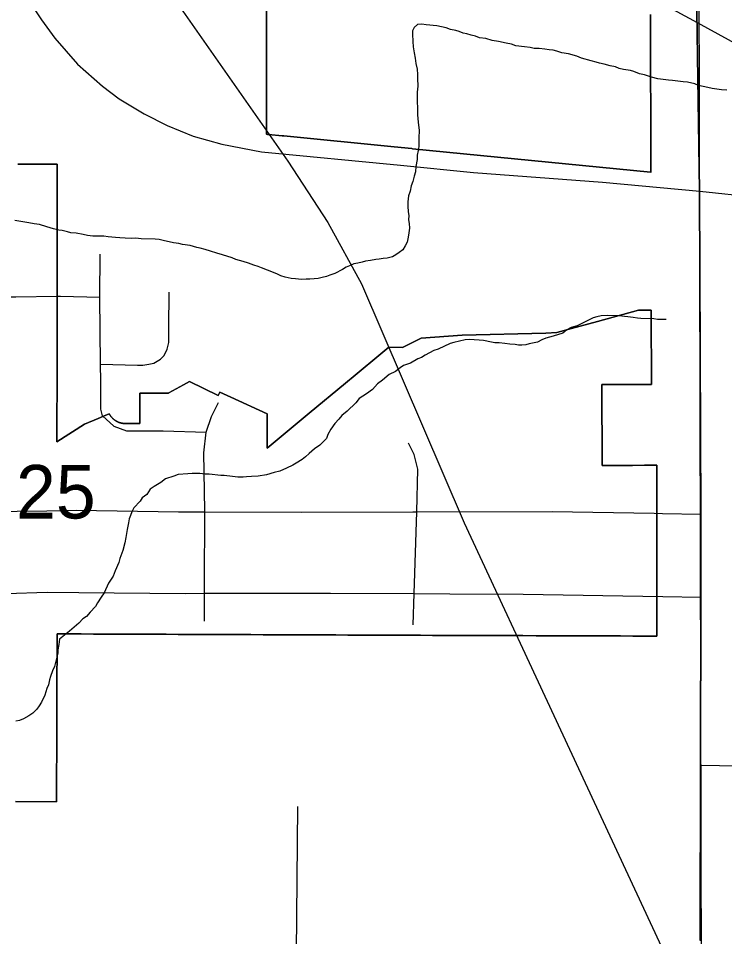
# Model space of a CAD drawing. Extents: x 0 to 34, y 0 to 22.
# Drawn here: x 2.497 to 3.049, y 18.646 to 19.364 of the extents above; entities that cross this region are included whole.
import ezdxf

# ---------------------------------------------------------------- set-up
doc = ezdxf.new("R2010")
doc.units = 0
for name, color, linetype in [('Default', 7, 'Continuous'), ('GM_X_City_Street', 7, 'Continuous'), ('GM_X_County_Road', 7, 'Continuous'), ('GM_X_Minor_River', 7, 'Continuous'), ('GM_X_Rail_Line', 7, 'Continuous'), ('GM_X_Section', 7, 'Continuous'), ('GM_X_Section_Text', 7, 'Continuous'), ('GM_X_State_Route', 7, 'Continuous'), ('GM_X_Township_Road', 7, 'Continuous')]:
    doc.layers.add(name, color=color, linetype=linetype)

msp = doc.modelspace()

# ---------------------------------------------------------------- linework, layer by layer
at = {"layer": 'Default'}
msp.add_lwpolyline([(2.1, 19.52883), (2.1, 18.51562), (3.03099, 18.49904), (3.02863, 19.51298)], close=True, dxfattribs=at)
at = {"layer": 'GM_X_City_Street'}
for p, q in [((2.52978, 19.14672), (2.56036, 19.14584)), ((3.00023, 18.97676), (3.03034, 18.97621)), ((3.00062, 18.91183), (3.03043, 18.9113))]:
    msp.add_line(p, q, dxfattribs=at)
for points in [[(2.5625, 19.05323), (2.56115, 19.05834), (2.56115, 19.08038), (2.561, 19.09346), (2.56036, 19.14584), (2.56062, 19.17953)], [(2.38459, 19.14607), (2.48317, 19.14612), (2.49488, 19.1463), (2.52672, 19.14681), (2.52978, 19.14672)], [(2.561, 19.09346), (2.58987, 19.09281), (2.59411, 19.09281), (2.59866, 19.09346), (2.60256, 19.09444), (2.60777, 19.09736), (2.6107, 19.1003), (2.61298, 19.10518), (2.61427, 19.11038), (2.61427, 19.12209), (2.6146, 19.14975)], [(2.64242, 18.97904), (2.64165, 19.02416), (2.64349, 19.04031), (2.64777, 19.05255), (2.65325, 19.06347)], [(2.5625, 19.05323), (2.57136, 19.04511), (2.58126, 19.04139), (2.61007, 19.04134), (2.64349, 19.04031)], [(2.80525, 18.88961), (2.80604, 18.91404), (2.80813, 18.97807), (2.80902, 19.01141), (2.80617, 19.02284), (2.80175, 19.03164)], [(2.33184, 18.8818), (2.34681, 18.88432), (2.3594, 18.88907), (2.37208, 18.90064), (2.39638, 18.92723), (2.41716, 18.94704), (2.43594, 18.96043), (2.45887, 18.97223), (2.48285, 18.97833), (2.49577, 18.97855), (2.51894, 18.97894)], [(2.51894, 18.97894), (2.542, 18.97934), (2.62199, 18.97814), (2.64244, 18.97808), (2.71827, 18.97784), (2.8051, 18.97806), (2.80813, 18.97807), (2.91391, 18.97833), (2.99369, 18.97688), (3.00023, 18.97676)], [(2.64233, 18.92108), (2.64244, 18.97808), (2.64242, 18.97904)], [(2.64227, 18.89242), (2.64232, 18.91432), (2.64233, 18.92108)], [(2.48716, 18.91411), (2.5194, 18.91514), (2.5441, 18.91495), (2.62706, 18.91429), (2.64232, 18.91432), (2.7408, 18.91449), (2.80604, 18.91404), (2.83405, 18.91385), (2.8913, 18.91376), (3.00062, 18.91183)], [(3.0302, 18.77983), (3.08849, 18.77885)], [(2.70841, 18.23919), (2.70934, 18.31177), (2.71042, 18.36903), (2.71381, 18.49764), (2.71286, 18.54198), (2.71361, 18.57587), (2.71511, 18.74755)]]:
    msp.add_lwpolyline(points, dxfattribs=at)
at = {"layer": 'GM_X_County_Road'}
for points in [[(3.02999, 18.64245), (3.0302, 18.77983), (3.03043, 18.9113), (3.03034, 18.97621), (3.02936, 19.22884), (3.02669, 19.40438)], [(2.50468, 19.37914), (2.50867, 19.37231), (2.51483, 19.36302), (2.52516, 19.34852), (2.54294, 19.32817), (2.56261, 19.31107), (2.57559, 19.30121), (2.59503, 19.28936), (2.61314, 19.28035), (2.63333, 19.27201), (2.6558, 19.26556), (2.6867, 19.25968), (2.79553, 19.24926), (2.85242, 19.24357), (2.95349, 19.23583), (3.02936, 19.22884)], [(3.02936, 19.22884), (3.07337, 19.22422), (3.10249, 19.21759), (3.13603, 19.20469), (3.1762, 19.1811), (3.20348, 19.15936), (3.21785, 19.14093), (3.26171, 19.08417), (3.29193, 19.05247), (3.33026, 19.0193), (3.37673, 18.9946), (3.41025, 18.98155), (3.46132, 18.96116), (3.5057, 18.94301), (3.5468, 18.92932), (3.57861, 18.91839), (3.61208, 18.90708), (3.66245, 18.88858), (3.70593, 18.87324), (3.73173, 18.8659), (3.81438, 18.84158)]]:
    msp.add_lwpolyline(points, dxfattribs=at)
at = {"layer": 'GM_X_Minor_River'}
for points in [[(3.05043, 19.30778), (3.04626, 19.30823), (3.03907, 19.30912), (3.03566, 19.30994), (3.02848, 19.31159), (3.02547, 19.31278), (3.0198, 19.31403), (3.01639, 19.31446), (3.00805, 19.31537), (3.00503, 19.31581), (2.99669, 19.31672), (2.99178, 19.31794), (2.98612, 19.31995), (2.98234, 19.32077), (2.97782, 19.32237), (2.97517, 19.32318), (2.96988, 19.32403), (2.96647, 19.32486), (2.96346, 19.32605), (2.9593, 19.32689), (2.95477, 19.3281), (2.95099, 19.32893), (2.94834, 19.32974), (2.94457, 19.33095), (2.93702, 19.33298), (2.93325, 19.33457), (2.92683, 19.3362), (2.92153, 19.33706), (2.91775, 19.33827), (2.91473, 19.33908), (2.91171, 19.33952), (2.9083, 19.33996), (2.90375, 19.34042), (2.89996, 19.34048), (2.89693, 19.3413), (2.89239, 19.34176), (2.88557, 19.34264), (2.88218, 19.34384), (2.87802, 19.34467), (2.87197, 19.34592), (2.86705, 19.34677), (2.86214, 19.34838), (2.85721, 19.34885), (2.8542, 19.35004), (2.8508, 19.35086), (2.84741, 19.35206), (2.84438, 19.3525), (2.84136, 19.35369), (2.83872, 19.3545), (2.83456, 19.35533), (2.83117, 19.35653), (2.82399, 19.35818), (2.81565, 19.35909), (2.81224, 19.35953), (2.80882, 19.35921), (2.80612, 19.35698), (2.80493, 19.35434), (2.80489, 19.35168), (2.80516, 19.34597), (2.80546, 19.34178), (2.80614, 19.33721), (2.80682, 19.33302)], [(2.80682, 19.33302), (2.8075, 19.32882), (2.80855, 19.32424), (2.80886, 19.32006), (2.8088, 19.31702), (2.80907, 19.31093), (2.8086, 19.30638), (2.80845, 19.29802), (2.80877, 19.29497), (2.80865, 19.28851), (2.80931, 19.2828), (2.80995, 19.27632), (2.80984, 19.27062), (2.80978, 19.26721), (2.80972, 19.26378), (2.80928, 19.26075), (2.80845, 19.25696), (2.80839, 19.25354), (2.80753, 19.24824), (2.80707, 19.24407), (2.80625, 19.24066), (2.80504, 19.2365), (2.80384, 19.2331), (2.803, 19.22893), (2.80179, 19.22515), (2.80133, 19.2206), (2.80126, 19.21718), (2.80156, 19.21261), (2.80189, 19.20995), (2.80183, 19.20653), (2.80215, 19.20348), (2.80246, 19.20005), (2.80202, 19.19626), (2.80157, 19.19285), (2.80075, 19.18906), (2.79917, 19.18605), (2.79722, 19.18304), (2.79452, 19.18081), (2.79183, 19.17896), (2.78914, 19.17748), (2.78495, 19.17642), (2.7819, 19.17609), (2.77886, 19.17577), (2.7762, 19.17543), (2.77201, 19.17475), (2.7682, 19.17405), (2.76553, 19.17334), (2.7621, 19.17264), (2.75905, 19.17194), (2.75561, 19.17048), (2.75293, 19.16939), (2.75024, 19.16753), (2.74411, 19.1646), (2.74029, 19.16315), (2.73761, 19.16205), (2.73418, 19.16135), (2.73114, 19.16065), (2.72809, 19.16032), (2.72467, 19.16), (2.72163, 19.16006), (2.71821, 19.15974), (2.71328, 19.16021), (2.70988, 19.16065), (2.70534, 19.16149), (2.70194, 19.16269), (2.69931, 19.16388), (2.69479, 19.16586), (2.6914, 19.16706), (2.68688, 19.16904), (2.68424, 19.16985), (2.68084, 19.17105), (2.6767, 19.17264), (2.67254, 19.17385), (2.66952, 19.17467), (2.66688, 19.17548), (2.66386, 19.17667), (2.65632, 19.17908), (2.65178, 19.18031), (2.64688, 19.18191), (2.64273, 19.18313), (2.63895, 19.18433), (2.6363, 19.18476), (2.63102, 19.18638), (2.62496, 19.18725), (2.62232, 19.18805), (2.61815, 19.18851), (2.60983, 19.19017), (2.60681, 19.19099), (2.60378, 19.19142), (2.59278, 19.19162), (2.58861, 19.19207), (2.58481, 19.19176), (2.58026, 19.19222), (2.57609, 19.19229), (2.57268, 19.19274), (2.56699, 19.19322), (2.56359, 19.19366), (2.55486, 19.19381), (2.55069, 19.19427), (2.54729, 19.19509), (2.54199, 19.19594)], [(2.54199, 19.19594), (2.53782, 19.1964), (2.53518, 19.1972), (2.53102, 19.19804), (2.52837, 19.19846), (2.52421, 19.1993), (2.51893, 19.20091), (2.51327, 19.20292), (2.5091, 19.20337), (2.50494, 19.2042), (2.497, 19.20549), (2.49397, 19.20592)], [(3.00308, 19.12844), (2.99625, 19.12857), (2.99361, 19.12899), (2.98336, 19.12917), (2.98071, 19.1296), (2.9773, 19.13004), (2.97314, 19.1305), (2.97049, 19.13092), (2.96632, 19.13138), (2.95721, 19.13154), (2.95227, 19.13125), (2.94884, 19.13055), (2.94617, 19.12984), (2.94081, 19.12727), (2.9366, 19.12507), (2.93353, 19.1236), (2.92895, 19.12216), (2.9255, 19.12032), (2.92241, 19.11771), (2.91478, 19.11557), (2.90906, 19.11377), (2.906, 19.11268), (2.90255, 19.11085), (2.89607, 19.10944), (2.8934, 19.10873), (2.89036, 19.1084), (2.8877, 19.10845), (2.88505, 19.10888), (2.88088, 19.10933), (2.8771, 19.10978), (2.87255, 19.11024), (2.86913, 19.1103), (2.86649, 19.11073), (2.86044, 19.11197), (2.85703, 19.11242), (2.84907, 19.11294), (2.84602, 19.11261), (2.83725, 19.11049), (2.8342, 19.10978), (2.82501, 19.10538), (2.82158, 19.1043), (2.81467, 19.10063), (2.81198, 19.09877), (2.80893, 19.09769), (2.80317, 19.09437), (2.79782, 19.09256), (2.79513, 19.09071), (2.79166, 19.08773), (2.78669, 19.08554), (2.78129, 19.08107), (2.77744, 19.0781), (2.77356, 19.07361), (2.76894, 19.07027), (2.76318, 19.06657), (2.76046, 19.0632), (2.75389, 19.05685), (2.74965, 19.05351), (2.74732, 19.05051), (2.74422, 19.04714), (2.7411, 19.04264), (2.73875, 19.0385), (2.73755, 19.03548), (2.73252, 19.03025), (2.72829, 19.02728), (2.72405, 19.02355), (2.72134, 19.02094), (2.71865, 19.01909), (2.71404, 19.01613), (2.71136, 19.01466), (2.70638, 19.01208), (2.70102, 19.0099), (2.69683, 19.00883), (2.69072, 19.00704), (2.68425, 19.00601), (2.67893, 19.00573), (2.67513, 19.00542), (2.67246, 19.00508), (2.66829, 19.00516), (2.66412, 19.00561), (2.65768, 19.00649), (2.65503, 19.00653), (2.64594, 19.00746), (2.6429, 19.00751), (2.63873, 19.00796), (2.63266, 19.00807), (2.62924, 19.00775), (2.62164, 19.00713), (2.6182, 19.00605), (2.61171, 19.00389), (2.60824, 19.0009), (2.60287, 18.99796), (2.59979, 18.99573), (2.59706, 18.9916), (2.59359, 18.989), (2.59202, 18.98637), (2.587, 18.98114), (2.58581, 18.9785), (2.58342, 18.97246), (2.58298, 18.96942), (2.58175, 18.96412), (2.58087, 18.95806)], [(2.58087, 18.95806), (2.58004, 18.95389), (2.57841, 18.94784), (2.57601, 18.94142), (2.5752, 18.93839), (2.57242, 18.93198), (2.57082, 18.92783), (2.5673, 18.92219), (2.56375, 18.91465), (2.56141, 18.91127), (2.55867, 18.90676), (2.5571, 18.90412), (2.55284, 18.89964), (2.55013, 18.89626), (2.54706, 18.89442), (2.54396, 18.89105), (2.53663, 18.88472), (2.52892, 18.8784), (2.52846, 18.87422), (2.52763, 18.87006), (2.52758, 18.8674), (2.52511, 18.85718), (2.52353, 18.85379), (2.52193, 18.84925), (2.52112, 18.84661), (2.52029, 18.84282), (2.5191, 18.8398), (2.51748, 18.83451), (2.51472, 18.82923), (2.51315, 18.82622), (2.5112, 18.8236), (2.50811, 18.82061), (2.50503, 18.81838), (2.50082, 18.81618), (2.49775, 18.81471), (2.49471, 18.81439)]]:
    msp.add_lwpolyline(points, dxfattribs=at)
at = {"layer": 'GM_X_Rail_Line'}
for points in [[(4.43224, 18.5911), (4.35401, 18.63374), (4.03896, 18.80642), (3.93636, 18.86252), (3.55446, 19.07184), (3.44627, 19.13121), (3.32905, 19.19548), (3.23414, 19.24733), (3.176, 19.27923), (3.12462, 19.30736), (3.02751, 19.36047), (2.90102, 19.42945), (2.74452, 19.51493), (2.65716, 19.56269), (2.57906, 19.60512), (2.43608, 19.68368), (2.39019, 19.70835), (2.24327, 19.78828)], [(2.38979, 19.70642), (2.70747, 19.25227), (2.73877, 19.20427), (2.76499, 19.15627), (2.84522, 18.96957), (3.19576, 18.2158), (3.25099, 18.10144), (3.28001, 18.04099), (3.32836, 17.99747), (3.36946, 17.95879), (3.44441, 17.92253), (3.72704, 17.80395), (4.02347, 17.68367)]]:
    msp.add_lwpolyline(points, dxfattribs=at)
at = {"layer": 'GM_X_Section'}
msp.add_lwpolyline([(3.02863, 19.51298), (4.05087, 19.50181), (4.05276, 18.48869), (3.03099, 18.49904)], close=True, dxfattribs=at)
at = {"layer": 'GM_X_State_Route'}
for points in [[(2.991, 19.36707), (2.99121, 19.24447), (2.99121, 19.2436), (2.99083, 19.24364), (2.80494, 19.26209), (2.80423, 19.26216), (2.79063, 19.26351), (2.7043, 19.27204), (2.70309, 19.27216), (2.69219, 19.27323), (2.69148, 19.2733), (2.69065, 19.27338), (2.69065, 19.27558), (2.69065, 19.29284), (2.69063, 19.37613)], [(2.69063, 19.37613), (2.69065, 19.29284), (2.69065, 19.29061), (2.69065, 19.27558), (2.69065, 19.27338), (2.69148, 19.2733), (2.69219, 19.27323), (2.70309, 19.27216), (2.7043, 19.27204), (2.79063, 19.26351), (2.80423, 19.26216), (2.80494, 19.26209), (2.99083, 19.24364), (2.99121, 19.24447), (2.991, 19.36707)], [(2.49635, 19.25005), (2.52713, 19.25012), (2.52715, 19.21206), (2.52716, 19.17687), (2.52714, 19.17403), (2.52713, 19.16551), (2.52711, 19.15131), (2.5271, 19.14663), (2.52709, 19.14184), (2.52707, 19.1276), (2.52705, 19.11627), (2.52703, 19.1049), (2.52703, 19.10431), (2.52702, 19.09354), (2.52701, 19.09266), (2.527, 19.08218), (2.527, 19.08101), (2.52698, 19.07081), (2.52698, 19.06936), (2.52696, 19.05789), (2.52696, 19.05772), (2.52694, 19.04607), (2.52692, 19.03442), (2.52692, 19.03281), (2.54856, 19.0467), (2.55905, 19.05108), (2.56335, 19.05288), (2.5678, 19.05474), (2.56804, 19.05431), (2.56817, 19.05409), (2.56829, 19.05388), (2.56842, 19.05367), (2.56856, 19.05346), (2.5687, 19.05326), (2.56884, 19.05305), (2.56899, 19.05285), (2.56914, 19.05266), (2.56929, 19.05246), (2.56944, 19.05227), (2.5696, 19.05208), (2.56977, 19.05189), (2.56993, 19.05171), (2.5701, 19.05152), (2.57036, 19.05126), (2.57054, 19.05108), (2.57072, 19.05091), (2.5709, 19.05074), (2.57109, 19.05058), (2.57128, 19.05042), (2.57147, 19.05026), (2.57166, 19.05011), (2.57186, 19.04996), (2.57206, 19.04981), (2.57226, 19.04966), (2.57246, 19.04952), (2.57267, 19.04939), (2.57288, 19.04925), (2.57309, 19.04912), (2.5733, 19.049), (2.57352, 19.04888), (2.57374, 19.04876), (2.57396, 19.04864), (2.57418, 19.04853), (2.5744, 19.04843), (2.57463, 19.04832), (2.57486, 19.04822), (2.57508, 19.04813), (2.57532, 19.04804), (2.57555, 19.04795), (2.57578, 19.04787), (2.57602, 19.04779), (2.57625, 19.04772), (2.57661, 19.04761), (2.57685, 19.04755), (2.57709, 19.04749), (2.57733, 19.04743), (2.57757, 19.04738), (2.57781, 19.04733), (2.57806, 19.04729), (2.5783, 19.04725), (2.57855, 19.04722), (2.57879, 19.04719), (2.57904, 19.04716), (2.57929, 19.04714), (2.57954, 19.04712), (2.57978, 19.04711), (2.58003, 19.0471), (2.5805, 19.04709), (2.59177, 19.04717), (2.59177, 19.07084), (2.59461, 19.07085), (2.60312, 19.07089), (2.61407, 19.07095), (2.61449, 19.07118), (2.62579, 19.07744), (2.63042, 19.07995), (2.65304, 19.06897), (2.65409, 19.07115), (2.65437, 19.07174), (2.66297, 19.06777), (2.69112, 19.05477), (2.69115, 19.05476), (2.69116, 19.05247), (2.6912, 19.04143), (2.69121, 19.03664), (2.69124, 19.02981), (2.69124, 19.0279), (2.7242, 19.05523), (2.75255, 19.07874), (2.75996, 19.08488), (2.78014, 19.10162), (2.78648, 19.10687), (2.79709, 19.10649), (2.81172, 19.11385), (2.84372, 19.11616), (2.90915, 19.1177), (2.91761, 19.11821), (2.92914, 19.12138), (2.94949, 19.12698), (2.98145, 19.13577), (2.99136, 19.13578), (2.99143, 19.12173), (2.99158, 19.08992), (2.99162, 19.08268), (2.99164, 19.07764), (2.95282, 19.0776), (2.95313, 19.01439), (2.95786, 19.01439), (2.96733, 19.0144), (2.9768, 19.01441), (2.98627, 19.01442), (2.99574, 19.01443), (2.99576, 19.00496), (2.99577, 18.99549), (2.99579, 18.98604), (2.9958, 18.98044), (2.9958, 18.97655), (2.99584, 18.95761), (2.99584, 18.95571), (2.99585, 18.94814), (2.99587, 18.93867), (2.99588, 18.9292), (2.9959, 18.91974), (2.99591, 18.91408), (2.99591, 18.91026), (2.99594, 18.89066), (2.99596, 18.88084), (2.98649, 18.88087), (2.98176, 18.88089), (2.97702, 18.8809), (2.96755, 18.88093), (2.95808, 18.88097), (2.94861, 18.881), (2.93914, 18.88103), (2.92967, 18.88106), (2.9202, 18.88109), (2.91073, 18.88112), (2.90147, 18.88116), (2.89102, 18.88119), (2.86792, 18.88127), (2.85845, 18.8813), (2.84898, 18.88133), (2.83951, 18.88136), (2.83418, 18.88138), (2.83004, 18.8814), (2.82057, 18.88143), (2.8111, 18.88146), (2.80164, 18.88149), (2.79217, 18.88153), (2.7827, 18.88157), (2.77323, 18.88161), (2.76376, 18.88164), (2.75429, 18.88168), (2.74482, 18.88172), (2.73535, 18.88176), (2.72588, 18.8818), (2.72142, 18.88181), (2.71641, 18.88184), (2.70694, 18.88187), (2.69747, 18.88191), (2.688, 18.88195), (2.67853, 18.88199), (2.66906, 18.88203), (2.65959, 18.88206), (2.65012, 18.8821), (2.64065, 18.88214), (2.63118, 18.88218), (2.62171, 18.88222), (2.61224, 18.88226), (2.60277, 18.88229), (2.60054, 18.8823), (2.5933, 18.88233), (2.58383, 18.88237), (2.57436, 18.88241), (2.56489, 18.88245), (2.55542, 18.88248), (2.54595, 18.88252), (2.53648, 18.88256), (2.53175, 18.88258), (2.52701, 18.8826), (2.52684, 18.83266), (2.52677, 18.81161), (2.52656, 18.75107), (2.49442, 18.75148)], [(2.49442, 18.75148), (2.52656, 18.75107), (2.52677, 18.81161), (2.52684, 18.83266), (2.52701, 18.8826), (2.53175, 18.88258), (2.53648, 18.88256), (2.54595, 18.88252), (2.55542, 18.88248), (2.56489, 18.88245), (2.57436, 18.88241), (2.58383, 18.88237), (2.5933, 18.88233), (2.60054, 18.8823), (2.60277, 18.88229), (2.61224, 18.88226), (2.62171, 18.88222), (2.63118, 18.88218), (2.64065, 18.88214), (2.65012, 18.8821), (2.65959, 18.88206), (2.66906, 18.88203), (2.67853, 18.88199), (2.688, 18.88195), (2.69747, 18.88191), (2.70694, 18.88187), (2.71641, 18.88184), (2.72142, 18.88181), (2.72588, 18.8818), (2.73535, 18.88176), (2.74482, 18.88172), (2.75429, 18.88168), (2.76376, 18.88164), (2.77323, 18.88161), (2.7827, 18.88157), (2.79217, 18.88153), (2.80164, 18.88149), (2.8111, 18.88146), (2.82057, 18.88143), (2.83004, 18.8814), (2.83418, 18.88138), (2.83951, 18.88136), (2.84898, 18.88133), (2.85845, 18.8813), (2.86792, 18.88127), (2.89102, 18.88119), (2.90147, 18.88116), (2.91073, 18.88112), (2.9202, 18.88109), (2.92967, 18.88106), (2.93914, 18.88103), (2.94861, 18.881), (2.95808, 18.88097), (2.96755, 18.88093), (2.97702, 18.8809), (2.98176, 18.88089), (2.98649, 18.88087), (2.99596, 18.88084), (2.99594, 18.89066), (2.99591, 18.91026), (2.99591, 18.91408), (2.9959, 18.91974), (2.99588, 18.9292), (2.99587, 18.93867), (2.99585, 18.94814), (2.99584, 18.95571), (2.99584, 18.95761), (2.9958, 18.97655), (2.9958, 18.98044), (2.99579, 18.98604), (2.99577, 18.99549), (2.99576, 19.00496), (2.99574, 19.01443), (2.98627, 19.01442), (2.9768, 19.01441), (2.96733, 19.0144), (2.95786, 19.01439), (2.95313, 19.01439), (2.95282, 19.0776), (2.99164, 19.07764), (2.99162, 19.08268), (2.99158, 19.08992), (2.99143, 19.12173), (2.99136, 19.13578), (2.98145, 19.13577), (2.94949, 19.12698), (2.92914, 19.12138), (2.91761, 19.11821), (2.90915, 19.1177), (2.84372, 19.11616), (2.81172, 19.11385), (2.79709, 19.10649), (2.78648, 19.10687), (2.78014, 19.10162), (2.75996, 19.08488), (2.75255, 19.07874), (2.7242, 19.05523), (2.69124, 19.0279), (2.69124, 19.02981), (2.69121, 19.03664), (2.6912, 19.04143), (2.69116, 19.05247), (2.69112, 19.05477), (2.66297, 19.06777), (2.65437, 19.07174), (2.65409, 19.07115), (2.65304, 19.06897), (2.63042, 19.07995), (2.62579, 19.07744), (2.61449, 19.07118), (2.61407, 19.07095), (2.60312, 19.07089), (2.59461, 19.07085), (2.59177, 19.07084), (2.59177, 19.04717), (2.5805, 19.04709), (2.58003, 19.0471), (2.57978, 19.04711), (2.57954, 19.04712), (2.57929, 19.04714), (2.57904, 19.04716), (2.57879, 19.04719), (2.57855, 19.04722), (2.5783, 19.04725), (2.57806, 19.04729), (2.57781, 19.04733), (2.57757, 19.04738), (2.57733, 19.04743), (2.57709, 19.04749), (2.57685, 19.04755), (2.57661, 19.04761), (2.57625, 19.04772), (2.57602, 19.04779), (2.57578, 19.04787), (2.57555, 19.04795), (2.57532, 19.04804), (2.57508, 19.04813), (2.57486, 19.04822), (2.57463, 19.04832), (2.5744, 19.04843), (2.57418, 19.04853), (2.57396, 19.04864), (2.57374, 19.04876), (2.57352, 19.04888), (2.5733, 19.049), (2.57309, 19.04912), (2.57288, 19.04925), (2.57267, 19.04939), (2.57246, 19.04952), (2.57226, 19.04966), (2.57206, 19.04981), (2.57186, 19.04996), (2.57166, 19.05011), (2.57147, 19.05026), (2.57128, 19.05042), (2.57109, 19.05058), (2.5709, 19.05074), (2.57072, 19.05091), (2.57054, 19.05108), (2.57036, 19.05126), (2.5701, 19.05152), (2.56993, 19.05171), (2.56977, 19.05189), (2.5696, 19.05208), (2.56944, 19.05227), (2.56929, 19.05246), (2.56914, 19.05266), (2.56899, 19.05285), (2.56884, 19.05305), (2.5687, 19.05326), (2.56856, 19.05346), (2.56842, 19.05367), (2.56829, 19.05388), (2.56817, 19.05409), (2.56804, 19.05431), (2.5678, 19.05474), (2.56335, 19.05288), (2.55905, 19.05108), (2.54856, 19.0467), (2.52692, 19.03281), (2.52694, 19.04607), (2.52696, 19.05772), (2.52696, 19.05789), (2.52698, 19.06936), (2.52698, 19.07081), (2.527, 19.08101), (2.527, 19.08218), (2.52701, 19.09266), (2.52702, 19.09354), (2.52703, 19.10431), (2.52703, 19.1049), (2.52705, 19.11627), (2.52707, 19.1276), (2.52709, 19.14184), (2.5271, 19.14663), (2.52711, 19.15131), (2.52713, 19.16551), (2.52714, 19.17214), (2.52714, 19.17403), (2.52716, 19.17687), (2.52715, 19.21206), (2.52713, 19.25012), (2.49635, 19.25005)]]:
    msp.add_lwpolyline(points, dxfattribs=at)
at = {"layer": 'GM_X_Township_Road'}
for points in [[(3.02646, 19.40492), (3.02912, 19.22937), (3.03011, 18.97674), (3.0302, 18.91183), (3.02996, 18.78036), (3.02976, 18.64299)], [(3.02976, 18.64299), (3.02996, 18.78036), (3.0302, 18.91183), (3.03011, 18.97674), (3.02912, 19.22937), (3.02646, 19.40492)]]:
    msp.add_lwpolyline(points, dxfattribs=at)

# ---------------------------------------------------------------- texts
at = {"layer": 'GM_X_Section_Text'}
msp.add_text('25', height=0.041856, rotation=0.00001, dxfattribs=at).set_placement((2.49494, 18.97283))

doc.saveas('drawing.dxf')
